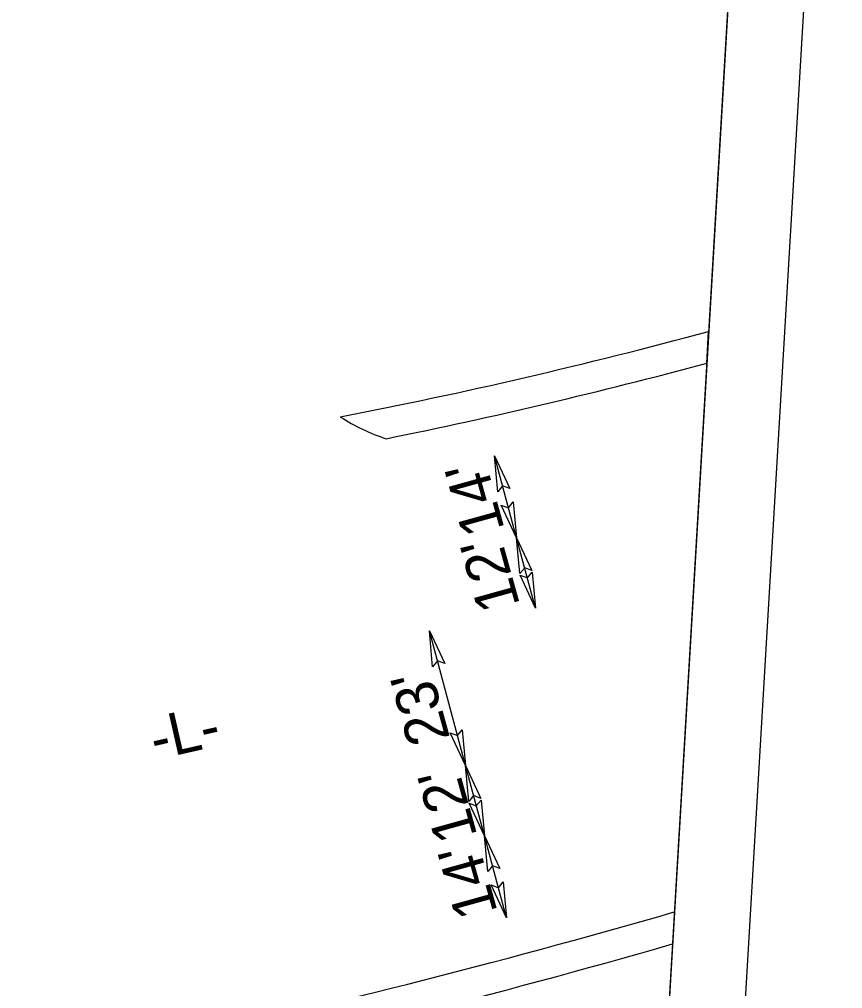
# Model space of a CAD drawing. Extents: x 2012744 to 2013625, y 444638 to 445237.
# Drawn here: x 2013488.7 to 2013624.5, y 444916.9 to 445076.8 of the extents above; entities that cross this region are included whole.
import ezdxf

# ---------------------------------------------------------------- set-up
doc = ezdxf.new("R2010")
doc.units = 0
for name, color, linetype in [('Prop Dimension', 7, 'Continuous'), ('Prop Dimension Text', 7, 'Continuous'), ('Prop Shade Medium', 7, 'Continuous'), ('Prop Terminator CELL', 7, 'Continuous'), ('Sheet Clip Boundary CELL', 7, 'Continuous'), ('Sheet Plan And Profile CELL', 7, 'Continuous'), ('Sheet Plot Border Outside CELL', 7, 'Continuous')]:
    doc.layers.add(name, color=color, linetype=linetype)

msp = doc.modelspace()

# ---------------------------------------------------------------- linework, layer by layer
at = {"layer": 'Prop Dimension'}
for p, q in [((2013570.74, 444991.27), (2013567.09, 445004.78)), ((2013573.88, 444979.68), (2013570.74, 444991.27)), ((2013562.31, 444953.67), (2013556.36, 444975.91)), ((2013565.44, 444942.08), (2013562.31, 444953.67)), ((2013569.1, 444928.57), (2013565.44, 444942.08))]:
    msp.add_line(p, q, dxfattribs=at)
at = {"layer": 'Prop Shade Medium'}
msp.add_line((2013602.1, 445020.07), (2013602.41, 445025.33), dxfattribs=at)
for centre, radius, start, end in [((2013377.03, 445857.87), 862.5, 281.00444, 285.14771), ((2013377.03, 445857.87), 867.5, 281.44766, 285.03711), ((2013559.55, 445038.96), 33, 237.1871, 251.729), ((2013223.9, 446217.91), 1341.25, 278.35841, 286.14038), ((2013223.9, 446217.91), 1346.25, 278.35841, 286.06498)]:
    msp.add_arc(centre, radius, start, end, dxfattribs=at)
at = {"layer": 'Prop Terminator CELL'}
for points in [[(2013567.64, 444998.87), (2013567.09, 445004.78), (2013569.63, 444999.38), (2013568.43, 444999.83)], [(2013570.19, 444997.18), (2013570.74, 444991.27), (2013568.2, 444996.68), (2013569.4, 444996.23)], [(2013571.3, 444985.36), (2013570.74, 444991.27), (2013573.28, 444985.86), (2013572.08, 444986.31)], [(2013573.32, 444985.59), (2013573.88, 444979.68), (2013571.34, 444985.09), (2013572.54, 444984.64)], [(2013556.89, 444970), (2013556.36, 444975.91), (2013558.88, 444970.5), (2013557.68, 444970.95)], [(2013561.77, 444959.58), (2013562.31, 444953.67), (2013559.78, 444959.08), (2013560.98, 444958.63)], [(2013562.86, 444947.76), (2013562.31, 444953.67), (2013564.85, 444948.26), (2013563.65, 444948.71)], [(2013564.89, 444947.99), (2013565.44, 444942.08), (2013562.9, 444947.49), (2013564.1, 444947.04)], [(2013566, 444936.17), (2013565.44, 444942.08), (2013567.98, 444936.67), (2013566.78, 444937.12)], [(2013568.54, 444934.48), (2013569.1, 444928.57), (2013566.56, 444933.97), (2013567.76, 444933.52)]]:
    msp.add_lwpolyline(points, close=True, dxfattribs=at)
at = {"layer": 'Sheet Clip Boundary CELL'}
for points in [[(2013605.95, 445084.18), (2013506.09, 445090.07), (2013509.49, 445147.63), (2013409.64, 445153.51), (2013411.6, 445186.8), (2012862.6, 445219.16), (2012831.71, 444695.07), (2013580.41, 444650.94)], [(2012832.37, 444695.56), (2012863.22, 445218.85), (2013411.41, 445186.54), (2013409.45, 445153.34), (2013509.31, 445147.45), (2013505.92, 445089.85), (2013605.86, 445083.96), (2013580.34, 444651.05)]]:
    msp.add_lwpolyline(points, close=True, dxfattribs=at)
at = {"layer": 'Sheet Plan And Profile CELL'}
msp.add_lwpolyline([(2013611.3, 445175.03), (2012862.6, 445219.16), (2012831.71, 444695.07), (2013580.41, 444650.94)], close=True, dxfattribs=at)
at = {"layer": 'Sheet Plot Border Outside CELL'}
msp.add_lwpolyline([(2012743.62, 444687.74), (2013592.15, 444637.73), (2013624.51, 445186.77), (2012775.99, 445236.79)], close=True, dxfattribs=at)

# ---------------------------------------------------------------- texts
at = {"layer": 'Prop Dimension'}
msp.add_text('-L-', height=7, rotation=12.7947, dxfattribs=at).set_placement((2013511.15, 444954.57))
at = {"layer": 'Prop Dimension Text'}
for s, rotation, p in [("14'", 105.5624, (2013568.8, 444992.68)), ("12'", 105.5624, (2013571.34, 444980.16)), ("23'", 105.4156, (2013559.8, 444958.19)), ("12'", 105.5624, (2013564.3, 444942.09)), ("14'", 105.5624, (2013567.64, 444929.52))]:
    msp.add_text(s, height=7, rotation=rotation, dxfattribs=at).set_placement(p)

doc.saveas('drawing.dxf')
